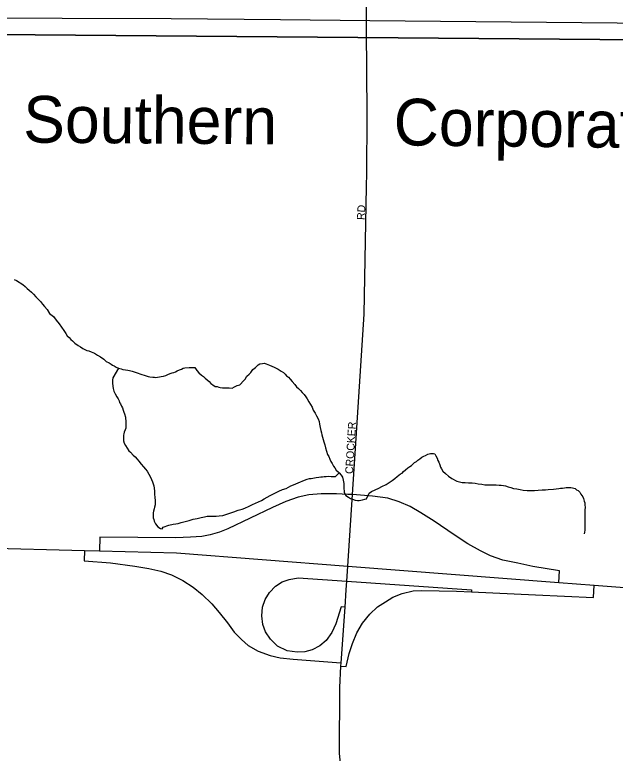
# Model space of a CAD drawing. Extents: x 2010165 to 2382125, y 1060529 to 1407316.
# Drawn here: x 2116938 to 2120777, y 1262787 to 1267507 of the extents above; entities that cross this region are included whole.
import ezdxf

# ---------------------------------------------------------------- set-up
doc = ezdxf.new("R2010")
doc.units = 0
for name, color, linetype in [('GM_X_City_Street', 7, 'Continuous'), ('GM_X_City_Street_Text', 7, 'Continuous'), ('GM_X_Corporation', 7, 'Continuous'), ('GM_X_Interchange_Ramps', 7, 'Continuous'), ('GM_X_Interstate_Route', 7, 'Continuous'), ('GM_X_Minor_River', 7, 'Continuous'), ('GM_X_Rail_Line', 7, 'Continuous'), ('GM_X_Rail_Line_Text', 7, 'Continuous')]:
    doc.layers.add(name, color=color, linetype=linetype)

msp = doc.modelspace()

# ---------------------------------------------------------------- linework, layer by layer
at = {"layer": 'GM_X_City_Street'}
for points in [[(2119186.9, 1267419.2), (2119186.2, 1267511.9), (2119214.4, 1268644.7), (2119215.2, 1268676.8), (2119215.3, 1268680.2), (2119222.9, 1269093.1), (2119228.9, 1269392.6), (2119244.1, 1270151.1), (2119255.1, 1270567.1), (2119264.7, 1270928), (2119285, 1271690.1), (2119285.8, 1271720), (2119298.5, 1272199), (2119322, 1273084.8)], [(2119187.1, 1266425.2), (2119189.1, 1266477.9), (2119190.8, 1266872.7), (2119186.9, 1267411.6), (2119186.9, 1267419.2)], [(2119057.1, 1263831.3), (2119061, 1263885.6), (2119067.8, 1263982), (2119097.6, 1264439.4), (2119121, 1264799.8), (2119170.5, 1265592.2), (2119186.5, 1266410), (2119187.1, 1266425.2)], [(2119072.7, 1262319.5), (2119038.5, 1262529.6), (2119013, 1262787.9), (2119015.7, 1263206.7), (2119022.2, 1263344.1), (2119023.7, 1263364.7), (2119049.2, 1263720.7), (2119057.1, 1263831.3)]]:
    msp.add_lwpolyline(points, dxfattribs=at)
at = {"layer": 'GM_X_Corporation'}
for points in [[(2140205.4, 1267168.3), (2121968.1, 1267337), (2113971.4, 1267404), (2113972.1, 1267511.1)], [(2113929.8, 1250070.4), (2113971.4, 1267404), (2121968.1, 1267337), (2140205.4, 1267168.3), (2140069, 1257837), (2140063.6, 1257468.8), (2140046.9, 1256760.6)]]:
    msp.add_lwpolyline(points, dxfattribs=at)
at = {"layer": 'GM_X_Interchange_Ramps'}
for points in [[(2119097.6, 1264439.4), (2119068.1, 1264440.5), (2118994.2, 1264444.6), (2118897.2, 1264444.4), (2118818.3, 1264438.4), (2118749.9, 1264424), (2118670.8, 1264395.7), (2118585.2, 1264356.8), (2118300.7, 1264221.9), (2118246.4, 1264198.8), (2118187, 1264181.8), (2118133.9, 1264171.6), (2118060.7, 1264167), (2117967.1, 1264162.4), (2117480.6, 1264167), (2117478.7, 1264080.3)], [(2120416, 1263878.2), (2120421.3, 1263953.4), (2120250.8, 1263980.9), (2120153.7, 1264000.9), (2120058.5, 1264020.6), (2119978.9, 1264048.4), (2119914.7, 1264080.2), (2119834.7, 1264124.8), (2119746.7, 1264183.1), (2119618.3, 1264269.3), (2119533.6, 1264323.6), (2119466.3, 1264363.2), (2119394.4, 1264394), (2119322.1, 1264415.8), (2119224.3, 1264430.4), (2119122.8, 1264438.5), (2119097.6, 1264439.4)], [(2117383, 1264082.7), (2117382.3, 1264017.3), (2117550.1, 1264003.6), (2117706.2, 1263983.1), (2117795.4, 1263968.3), (2117871.6, 1263949.7), (2117940.3, 1263927.4), (2118012.8, 1263890.2), (2118077.8, 1263847.4), (2118135.4, 1263801), (2118196.7, 1263741.5), (2118245, 1263685.8), (2118297, 1263620.7), (2118339.8, 1263559.3), (2118386.2, 1263512.9), (2118430.8, 1263475.7), (2118494, 1263438.5), (2118570.1, 1263410.7), (2118635.2, 1263395.8), (2118716.9, 1263388.4), (2118994.9, 1263366.5), (2119023.7, 1263364.7)], [(2119049.2, 1263720.7), (2119023.8, 1263722.3), (2118990, 1263613.3), (2118964, 1263557.5), (2118928.7, 1263507.3), (2118887.9, 1263473.9), (2118839.5, 1263447.9), (2118793.1, 1263434.8), (2118742.9, 1263433), (2118679.8, 1263440.4), (2118618.4, 1263470.1), (2118572, 1263516.6), (2118540.4, 1263563.1), (2118523.7, 1263609.5), (2118516.3, 1263665.3), (2118521.8, 1263719.2), (2118538.5, 1263769.4), (2118566.4, 1263814), (2118605.4, 1263854.9), (2118646.3, 1263882.8), (2118692.7, 1263897.6), (2118750.4, 1263906.9), (2119061, 1263885.6), (2119857.7, 1263830.7), (2119857.1, 1263817.2)], [(2119022.2, 1263344.1), (2119056.9, 1263341.9), (2119075.5, 1263423.7), (2119095.9, 1263488.7), (2119123.8, 1263555.6), (2119161, 1263617), (2119207.4, 1263674.6), (2119257.6, 1263722.9), (2119307.7, 1263754.5), (2119354.2, 1263784.3), (2119415.5, 1263806.6), (2119484.2, 1263825.2), (2119540, 1263827), (2119761.1, 1263821.4), (2119857.1, 1263817.2), (2120266.4, 1263799.1), (2120637.7, 1263782), (2120643.1, 1263860.8)]]:
    msp.add_lwpolyline(points, dxfattribs=at)
at = {"layer": 'GM_X_Interstate_Route'}
for points in [[(2116731.7, 1264099.2), (2117383, 1264082.7), (2117478.7, 1264080.3), (2117972.6, 1264067.8), (2119067.8, 1263982)], [(2119067.8, 1263982), (2120416, 1263878.2), (2120643.1, 1263860.8), (2121779.1, 1263773.4), (2123721.8, 1263614.6)]]:
    msp.add_lwpolyline(points, dxfattribs=at)
at = {"layer": 'GM_X_Minor_River'}
for points in [[(2116933.1, 1265813.7), (2116949.2, 1265807.8), (2116989.4, 1265781.8), (2117003.5, 1265769.8), (2117017.6, 1265757.8), (2117029.7, 1265745.8), (2117043.8, 1265733.8), (2117057.9, 1265719.8), (2117072, 1265703.8), (2117086.1, 1265689.8), (2117102.2, 1265673.8), (2117114.3, 1265657.8), (2117128.4, 1265641.8)], [(2117128.4, 1265641.8), (2117144.5, 1265623.8), (2117160.6, 1265597.7), (2117184.8, 1265577.7), (2117202.9, 1265553.7), (2117221.1, 1265531.7), (2117237.2, 1265509.7), (2117251.3, 1265489.6), (2117263.4, 1265469.6), (2117273.5, 1265453.6), (2117285.6, 1265443.6), (2117295.6, 1265431.6), (2117307.7, 1265421.6), (2117321.8, 1265407.6), (2117343.9, 1265393.6), (2117358, 1265383.6), (2117372.1, 1265373.7), (2117386.2, 1265367.7), (2117398.2, 1265361.7), (2117410.3, 1265357.7), (2117426.4, 1265351.8), (2117446.5, 1265343.8), (2117466.6, 1265331.8), (2117486.7, 1265319.8), (2117506.8, 1265305.9), (2117522.9, 1265289.9), (2117541, 1265281.9), (2117553.1, 1265273.9), (2117563.1, 1265267.9), (2117573.2, 1265261.9), (2117585.2, 1265253.9), (2117601.3, 1265248), (2117617.4, 1265244), (2117629.4, 1265240), (2117645.5, 1265236.1), (2117659.5, 1265234.1), (2117671.6, 1265232.1), (2117687.7, 1265228.2), (2117701.7, 1265224.2), (2117713.8, 1265220.2), (2117749.9, 1265208.3), (2117764, 1265202.3), (2117778.1, 1265198.4), (2117790.1, 1265194.4), (2117802.2, 1265192.4), (2117820.2, 1265190.5), (2117830.3, 1265190.5), (2117840.3, 1265188.5), (2117850.3, 1265190.6), (2117862.4, 1265192.6), (2117874.4, 1265194.7), (2117888.4, 1265196.7), (2117902.5, 1265200.8), (2117916.5, 1265206.8), (2117930.5, 1265212.9), (2117944.6, 1265219), (2117954.6, 1265221), (2117964.6, 1265225.1), (2117976.6, 1265231.1), (2117990.6, 1265237.2), (2118002.7, 1265241.2), (2118014.7, 1265247.3), (2118024.7, 1265249.3), (2118052.8, 1265251.4), (2118072.9, 1265251.5), (2118088.9, 1265251.5), (2118101, 1265233.5), (2118115.1, 1265217.5), (2118131.2, 1265203.5), (2118143.3, 1265193.5), (2118155.4, 1265183.5), (2118167.5, 1265173.5), (2118179.5, 1265161.5), (2118191.6, 1265149.5), (2118203.7, 1265141.5), (2118219.8, 1265131.6), (2118231.8, 1265129.6), (2118241.9, 1265125.6), (2118251.9, 1265123.6), (2118266, 1265121.7), (2118288, 1265121.7), (2118308.1, 1265121.8), (2118328.2, 1265119.8), (2118342.2, 1265127.9), (2118360.2, 1265136), (2118376.3, 1265142.1), (2118402.3, 1265168.2), (2118410.2, 1265178.3), (2118422.2, 1265196.4), (2118436.2, 1265210.5), (2118446.2, 1265220.6), (2118460.2, 1265238.7), (2118476.2, 1265252.8), (2118494.2, 1265268.9), (2118504.2, 1265274.9), (2118522.3, 1265277), (2118532.3, 1265279), (2118544.4, 1265275.1), (2118566.5, 1265267.1), (2118596.6, 1265255.1), (2118622.7, 1265241.2)], [(2117600.9, 1265248.1), (2117565.4, 1265185.6), (2117563.4, 1265171.6), (2117563.5, 1265151.5), (2117565.6, 1265133.5), (2117567.6, 1265117.4), (2117571.7, 1265101.4), (2117579.8, 1265083.4), (2117589.9, 1265065.3), (2117598, 1265051.3), (2117604, 1265039.3), (2117608.1, 1265029.3), (2117614.1, 1265019.3), (2117620.2, 1265005.2), (2117626.3, 1264995.2), (2117630.3, 1264979.2), (2117634.4, 1264967.1), (2117638.4, 1264955.1), (2117644.5, 1264935.1), (2117646.6, 1264923.1), (2117648.6, 1264913), (2117648.7, 1264899), (2117648.7, 1264878.9), (2117646.8, 1264864.9), (2117642.8, 1264852.8), (2117636.8, 1264838.7), (2117634.9, 1264828.7), (2117632.9, 1264818.7), (2117632.9, 1264808.6), (2117633, 1264796.6), (2117633, 1264782.5), (2117637.1, 1264768.5), (2117645.2, 1264752.5), (2117655.3, 1264736.5), (2117667.4, 1264718.4), (2117677.4, 1264710.4), (2117695.5, 1264692.4), (2117707.6, 1264680.4), (2117719.7, 1264666.4), (2117731.8, 1264652.4), (2117745.9, 1264634.4), (2117760, 1264616.4), (2117774.1, 1264602.4), (2117784.2, 1264588.4), (2117806.4, 1264550.3), (2117812.5, 1264536.3), (2117818.5, 1264522.3), (2117822.6, 1264508.2), (2117826.7, 1264496.2), (2117828.7, 1264480.2), (2117830.8, 1264462.1), (2117830.9, 1264442.1), (2117832.9, 1264422), (2117835, 1264401.9), (2117835.1, 1264387.9), (2117835.1, 1264373.8), (2117831.1, 1264359.8), (2117829.2, 1264349.7), (2117825.2, 1264333.7), (2117823.2, 1264323.6), (2117823.3, 1264313.6), (2117823.3, 1264303.6), (2117823.3, 1264291.5), (2117827.4, 1264281.5), (2117829.4, 1264269.5), (2117837.5, 1264253.4), (2117851.6, 1264233.4), (2117869.7, 1264223.4), (2117879.8, 1264221.5), (2117885.8, 1264231.5), (2117921.8, 1264243.7), (2117949.9, 1264249.8), (2117968, 1264251.9), (2117982, 1264255.9), (2118002.1, 1264262), (2118026.1, 1264268.1), (2118052.2, 1264274.2), (2118078.2, 1264282.3), (2118104.3, 1264286.4), (2118128.4, 1264292.5), (2118150.4, 1264296.6), (2118168.5, 1264302.7), (2118190.5, 1264302.7), (2118206.6, 1264302.8), (2118224.6, 1264302.8), (2118244.7, 1264302.9), (2118268.8, 1264307), (2118338.9, 1264329.3), (2118365, 1264339.4), (2118391.1, 1264347.5), (2118409.1, 1264353.6), (2118437.1, 1264365.7), (2118457.2, 1264375.8), (2118477.2, 1264383.9), (2118495.2, 1264394), (2118515.3, 1264402.1)], [(2118622.7, 1265241.2), (2118640.8, 1265229.2), (2118654.9, 1265219.2), (2118667, 1265209.2), (2118675.1, 1265199.2), (2118687.1, 1265189.2), (2118699.2, 1265177.2), (2118711.3, 1265163.2), (2118727.4, 1265143.2), (2118739.5, 1265129.2), (2118751.6, 1265117.2), (2118763.7, 1265105.2), (2118775.8, 1265091.2), (2118787.9, 1265079.2), (2118797.9, 1265065.2), (2118808, 1265051.1), (2118818.1, 1265033.1), (2118828.2, 1265015.1), (2118838.3, 1264999.1), (2118846.4, 1264979), (2118858.5, 1264961), (2118866.6, 1264943), (2118876.7, 1264924.9), (2118882.8, 1264906.9), (2118886.8, 1264888.9), (2118890.9, 1264868.8), (2118895, 1264848.8), (2118899.1, 1264834.7), (2118901.1, 1264820.7), (2118913.3, 1264776.6), (2118919.4, 1264758.5), (2118923.5, 1264738.5), (2118931.6, 1264716.4), (2118937.7, 1264696.4), (2118945.8, 1264682.4), (2118951.8, 1264666.3), (2118957.9, 1264650.3), (2118966, 1264638.3), (2118976.1, 1264622.3), (2118984.1, 1264610.2), (2118992.2, 1264596.2), (2119004.3, 1264584.2), (2119011.4, 1264579.2)], [(2119265.2, 1264481.6), (2119283.5, 1264490.8), (2119311.6, 1264504.9), (2119331.6, 1264517), (2119349.6, 1264529.1), (2119367.6, 1264543.2), (2119381.6, 1264555.3), (2119393.7, 1264563.4), (2119403.7, 1264571.4), (2119413.7, 1264577.5), (2119423.7, 1264587.6), (2119435.7, 1264597.6), (2119449.7, 1264609.7), (2119463.7, 1264619.8), (2119473.7, 1264625.8), (2119493.7, 1264644), (2119505.7, 1264652), (2119515.7, 1264660.1), (2119527.7, 1264668.2), (2119539.7, 1264678.2), (2119553.8, 1264684.3), (2119563.8, 1264690.3), (2119577.8, 1264698.4), (2119595.8, 1264702.5), (2119613.9, 1264702.5), (2119623.9, 1264700.6), (2119630, 1264686.5), (2119638.1, 1264672.5), (2119642.2, 1264658.5), (2119648.2, 1264646.5), (2119654.3, 1264630.4), (2119660.4, 1264614.4), (2119666.4, 1264604.4), (2119674.5, 1264590.4), (2119690.6, 1264574.4), (2119710.7, 1264558.4), (2119732.9, 1264542.4), (2119763, 1264526.4), (2119781.1, 1264520.5), (2119799.2, 1264516.5), (2119817.2, 1264516.6), (2119839.3, 1264514.6), (2119861.4, 1264514.7), (2119881.5, 1264512.8), (2119901.5, 1264508.8), (2119923.6, 1264506.9), (2119943.7, 1264502.9), (2119963.8, 1264503), (2119985.8, 1264501.1), (2120015.9, 1264501.1), (2120034, 1264499.2), (2120048.1, 1264499.2), (2120062.1, 1264497.3), (2120076.2, 1264495.3), (2120092.2, 1264489.3), (2120108.3, 1264485.4), (2120126.4, 1264479.4), (2120148.5, 1264475.5), (2120168.6, 1264471.5), (2120188.6, 1264467.6), (2120214.7, 1264465.6), (2120236.8, 1264465.7), (2120260.9, 1264465.8), (2120285, 1264467.9), (2120309, 1264470), (2120331.1, 1264470), (2120347.1, 1264472.1), (2120381.3, 1264474.2), (2120399.3, 1264476.3), (2120415.3, 1264478.3), (2120427.4, 1264480.4), (2120439.4, 1264480.4), (2120451.5, 1264482.5), (2120463.5, 1264484.5), (2120479.6, 1264484.6), (2120493.6, 1264484.6), (2120503.6, 1264482.6), (2120519.7, 1264478.7), (2120529.8, 1264470.7), (2120539.8, 1264466.7), (2120549.9, 1264454.7), (2120557.9, 1264442.7), (2120570.1, 1264424.6), (2120574.1, 1264414.6), (2120578.2, 1264398.6), (2120582.2, 1264386.6), (2120582.3, 1264372.5), (2120584.3, 1264358.5), (2120582.4, 1264340.4), (2120582.4, 1264324.3), (2120582.5, 1264306.3), (2120582.5, 1264292.2), (2120582.6, 1264278.2), (2120582.7, 1264258.1)], [(2118515.3, 1264402.1), (2118531.3, 1264412.2), (2118551.3, 1264424.3), (2118571.4, 1264434.4), (2118587.4, 1264442.4), (2118605.4, 1264450.5), (2118625.4, 1264460.6), (2118649.5, 1264472.7), (2118673.5, 1264478.8), (2118687.6, 1264486.9), (2118703.6, 1264495), (2118719.6, 1264503.1), (2118733.6, 1264509.1), (2118749.7, 1264515.2), (2118763.7, 1264521.3), (2118775.7, 1264525.3), (2118789.8, 1264531.4), (2118807.8, 1264537.4), (2118821.8, 1264541.5), (2118831.9, 1264541.5), (2118843.9, 1264545.6), (2118863.9, 1264549.7), (2118882, 1264551.7), (2118894, 1264553.8), (2118904.1, 1264553.8), (2118916.1, 1264555.9), (2118928.1, 1264555.9), (2118944.2, 1264557.9), (2118960.2, 1264556), (2118976.3, 1264556), (2118988.3, 1264556.1), (2119011.4, 1264579.2)], [(2119011.3, 1264579.2), (2119012.3, 1264578.2), (2119024.4, 1264564.2), (2119032.5, 1264550.2), (2119036.6, 1264532.2), (2119038.6, 1264522.1), (2119040.7, 1264510.1), (2119040.7, 1264498.1), (2119040.7, 1264486), (2119042.9, 1264455.9), (2119048.9, 1264443.9), (2119055, 1264433.9), (2119071.1, 1264423.9), (2119085.1, 1264413.9), (2119097.2, 1264409.9), (2119113.3, 1264404), (2119129.3, 1264402), (2119139.4, 1264402.1), (2119149.4, 1264404.1), (2119161.4, 1264406.1), (2119175.5, 1264410.2), (2119185.5, 1264412.2), (2119203.4, 1264448.4), (2119217.4, 1264458.5), (2119265.2, 1264481.6)], [(2120582.7, 1264258.1), (2120582.7, 1264240.1), (2120582.8, 1264226), (2120582.8, 1264212), (2120580.9, 1264199.9), (2120578.9, 1264187.9), (2120578.9, 1264187.9)]]:
    msp.add_lwpolyline(points, dxfattribs=at)
at = {"layer": 'GM_X_Rail_Line'}
msp.add_lwpolyline([(2113972.9, 1267502.1), (2117240.2, 1267485.7), (2117936.8, 1267482.1), (2118637, 1267476.4), (2119207.2, 1267469.2), (2120788.3, 1267454.9), (2122004.3, 1267442.8), (2123412.6, 1267429.2), (2125388.1, 1267409.2), (2126127.6, 1267400.6), (2127231.4, 1267389.9), (2130406.6, 1267359.9), (2132736.5, 1267337.1), (2134810.6, 1267317.8), (2139871.2, 1267271.3), (2143552.9, 1267237)], dxfattribs=at)

# ---------------------------------------------------------------- texts
at = {"layer": 'GM_X_City_Street_Text'}
for s, rotation, p in [('RD', 86.989, (2119174.6, 1266194)), ('CROCKER', 86.5826, (2119099.8, 1264570.4))]:
    msp.add_text(s, height=50, rotation=rotation, dxfattribs=at).set_placement(p)
at = {"layer": 'GM_X_Rail_Line_Text'}
for s, rotation, p in [('Southern', 359.5843, (2116990.8, 1266689.9)), ('Corporation', 359.3596, (2119358.9, 1266672.4))]:
    msp.add_text(s, height=299, rotation=rotation, dxfattribs=at).set_placement(p)

doc.saveas('drawing.dxf')
